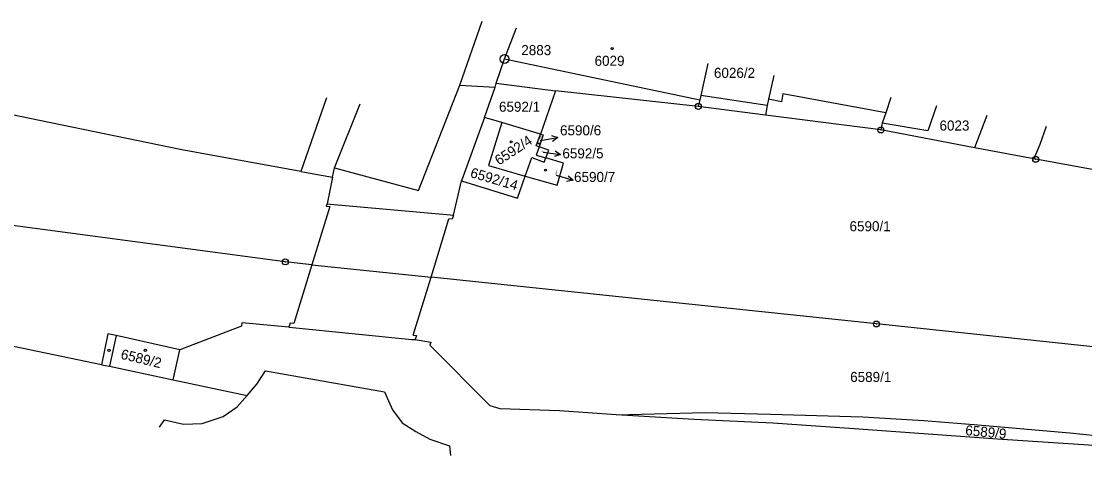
# Model space of a CAD drawing. Extents: x -825057 to -819383, y -1071633 to -1067888.
# Drawn here: x -823032.3 to -822852.6, y -1070471.3 to -1070394.3 of the extents above; entities that cross this region are included whole.
import ezdxf

# ---------------------------------------------------------------- set-up
doc = ezdxf.new("R2010")
doc.units = 0
for name, color, linetype in [('Vrstva 1', 7, 'Continuous'), ('Vrstva 16', 7, 'Continuous'), ('Vrstva 17', 7, 'Continuous'), ('Vrstva 18', 7, 'Continuous'), ('Vrstva 19', 7, 'Continuous'), ('Vrstva 24', 7, 'Continuous'), ('Vrstva 25', 7, 'Continuous'), ('Vrstva 4', 7, 'Continuous')]:
    doc.layers.add(name, color=color, linetype=linetype)

msp = doc.modelspace()

# ---------------------------------------------------------------- linework, layer by layer
at = {"layer": 'Vrstva 1'}
for p, q in [((-822958.18, -1070405.1), (-822954.43, -1070394.29)), ((-822950.64, -1070400.67), (-822948.61, -1070395.38)), ((-823005.47, -1070416), (-823077.88, -1070401.08)), ((-822952.05, -1070404.75), (-822950.64, -1070400.67)), ((-822916.25, -1070401.42), (-822917.46, -1070406.85)), ((-822905.12, -1070403.49), (-822906, -1070407.45)), ((-822965.18, -1070422.9), (-822958.18, -1070405.1)), ((-822958.18, -1070405.1), (-822952.21, -1070405.45)), ((-822952.21, -1070405.45), (-822952.05, -1070404.75)), ((-822952.05, -1070404.75), (-822942, -1070406.08)), ((-822954.04, -1070410.56), (-822952.21, -1070405.45)), ((-822942, -1070406.08), (-822944.55, -1070413.39)), ((-822917.88, -1070408.69), (-822942, -1070406.08)), ((-822917.46, -1070406.85), (-822917.63, -1070407.6)), ((-822980.71, -1070407.22), (-822985.08, -1070419.69)), ((-822979.37, -1070419.1), (-822975.05, -1070408.25)), ((-822917.63, -1070407.6), (-822917.88, -1070408.69)), ((-822906.54, -1070410.15), (-822917.88, -1070408.69)), ((-822906.23, -1070408.52), (-822906.54, -1070410.15)), ((-822906, -1070407.45), (-822906.23, -1070408.52)), ((-822885.33, -1070407.19), (-822886.19, -1070409.78)), ((-822877.65, -1070408.62), (-822879.08, -1070412.8)), ((-822954.04, -1070410.56), (-822957.9, -1070421.3)), ((-822951.08, -1070411.44), (-822954.04, -1070410.56)), ((-822887.02, -1070412.68), (-822906.54, -1070410.15)), ((-822886.19, -1070409.78), (-822886.8, -1070411.54)), ((-822869.1, -1070410.21), (-822871.2, -1070415.68)), ((-822951.08, -1070411.44), (-822953.36, -1070418.69)), ((-822944.55, -1070413.39), (-822951.08, -1070411.44)), ((-822886.8, -1070411.54), (-822887.02, -1070412.68)), ((-822879.08, -1070412.8), (-822886.8, -1070411.54)), ((-822859.11, -1070412.08), (-822860.15, -1070415.14)), ((-822945.27, -1070415.37), (-822944.55, -1070413.39)), ((-822944.12, -1070413.52), (-822944.8, -1070415.54)), ((-822944.55, -1070413.39), (-822944.12, -1070413.52)), ((-822871.2, -1070415.68), (-822887.02, -1070412.68)), ((-822999.3, -1070417.12), (-823005.47, -1070416)), ((-822944.8, -1070415.54), (-822945.27, -1070415.37)), ((-822944.8, -1070415.54), (-822945.26, -1070416.93)), ((-822943.15, -1070416.12), (-822944.8, -1070415.54)), ((-822943.63, -1070417.4), (-822943.15, -1070416.12)), ((-822861.2, -1070417.58), (-822871.2, -1070415.68)), ((-822860.15, -1070415.14), (-822861.2, -1070417.58)), ((-822989.08, -1070418.97), (-822999.3, -1070417.12)), ((-822947.14, -1070420.48), (-822946.02, -1070417.36)), ((-822946.02, -1070417.36), (-822943.91, -1070418.12)), ((-822945.26, -1070416.93), (-822943.63, -1070417.4)), ((-822943.91, -1070418.12), (-822943.63, -1070417.4)), ((-822940.65, -1070418.27), (-822943.63, -1070417.4)), ((-822860.86, -1070417.64), (-822861.2, -1070417.58)), ((-822850.06, -1070419.61), (-822860.86, -1070417.64)), ((-822985.08, -1070419.69), (-822989.08, -1070418.97)), ((-822985.08, -1070419.69), (-822979.69, -1070420.66)), ((-822979.69, -1070420.66), (-822979.37, -1070419.1)), ((-822979.37, -1070419.1), (-822965.18, -1070422.9)), ((-822953.36, -1070418.69), (-822947.14, -1070420.48)), ((-822941.76, -1070422.02), (-822940.65, -1070418.27)), ((-822979.69, -1070420.66), (-822980.63, -1070425.16)), ((-822957.9, -1070421.3), (-822948.46, -1070424.2)), ((-822948.46, -1070424.2), (-822947.14, -1070420.48)), ((-822947.14, -1070420.48), (-822941.76, -1070422.02)), ((-822987.68, -1070435), (-823086.47, -1070421.85)), ((-822980.15, -1070425.64), (-822983.18, -1070435.48)), ((-822980.63, -1070425.16), (-822980.75, -1070425.57)), ((-822980.75, -1070425.57), (-822980.15, -1070425.64)), ((-822983.18, -1070435.48), (-822987.68, -1070435)), ((-822983.18, -1070435.48), (-822986.24, -1070445.4)), ((-822983.18, -1070435.48), (-822963.05, -1070437.59)), ((-822887.77, -1070445.5), (-822963.05, -1070437.59)), ((-822995.09, -1070445.89), (-823005.51, -1070449.87)), ((-822995.03, -1070445.29), (-822995.09, -1070445.89)), ((-822987.07, -1070446.06), (-822995.03, -1070445.29)), ((-822986.85, -1070445.34), (-822987.07, -1070446.06)), ((-822987.07, -1070446.06), (-822986.47, -1070446.12)), ((-822986.24, -1070445.4), (-822986.85, -1070445.34)), ((-822986.47, -1070446.12), (-822966.27, -1070448.1)), ((-822788.26, -1070456.02), (-822887.77, -1070445.5)), ((-823018.74, -1070452.4), (-823045.87, -1070446.73)), ((-823017.65, -1070447.17), (-823018.74, -1070452.4)), ((-823016.29, -1070447.45), (-823017.65, -1070447.17)), ((-823005.51, -1070449.87), (-823016.29, -1070447.45)), ((-822966.27, -1070448.1), (-822965.74, -1070448.15)), ((-822965.74, -1070448.15), (-822963.08, -1070448.59)), ((-823006.65, -1070454.95), (-823005.51, -1070449.87)), ((-822963.08, -1070448.59), (-822963.26, -1070449.09)), ((-822963.26, -1070449.09), (-822953.06, -1070459.32)), ((-823018.74, -1070452.4), (-823017.4, -1070452.64)), ((-823017.4, -1070452.64), (-823006.65, -1070454.95)), ((-822992.52, -1070455.67), (-822991.01, -1070453.41)), ((-822991.01, -1070453.41), (-822970.89, -1070456.95)), ((-823006.65, -1070454.95), (-822994.1, -1070457.58)), ((-822994.1, -1070457.58), (-822992.52, -1070455.67)), ((-822970.89, -1070456.95), (-822969.59, -1070460.01)), ((-822995.82, -1070459.51), (-822994.1, -1070457.58)), ((-822998.21, -1070461.16), (-822995.82, -1070459.51)), ((-822969.59, -1070460.01), (-822967.92, -1070462.24)), ((-822951.35, -1070459.84), (-822953.06, -1070459.32)), ((-822941.35, -1070460.21), (-822951.35, -1070459.84)), ((-822931.79, -1070460.84), (-822941.35, -1070460.21)), ((-822931.79, -1070460.84), (-822916.73, -1070460.47)), ((-822927.98, -1070461.09), (-822931.79, -1070460.84)), ((-822918.56, -1070461.67), (-822927.98, -1070461.09)), ((-822916.73, -1070460.47), (-822905.69, -1070460.76)), ((-822905.69, -1070460.76), (-822890.07, -1070461.21)), ((-823008.97, -1070462.97), (-823008.11, -1070461.69)), ((-823008.11, -1070461.69), (-823004.87, -1070462.46)), ((-823004.87, -1070462.46), (-823001.75, -1070462.34)), ((-823001.75, -1070462.34), (-822998.21, -1070461.16)), ((-822967.92, -1070462.24), (-822965.63, -1070463.7)), ((-822905.29, -1070462.29), (-822918.56, -1070461.67)), ((-822891.54, -1070463.24), (-822905.29, -1070462.29)), ((-822890.07, -1070461.21), (-822879.77, -1070461.85)), ((-822879.77, -1070461.85), (-822871.29, -1070462.48)), ((-822871.29, -1070462.48), (-822855.09, -1070463.92)), ((-822965.63, -1070463.7), (-822963.28, -1070464.96)), ((-822867.3, -1070464.97), (-822891.54, -1070463.24)), ((-822855.09, -1070463.92), (-822780.34, -1070471.34)), ((-822963.28, -1070464.96), (-822959.93, -1070466.13)), ((-822959.93, -1070466.13), (-822959.74, -1070467.75)), ((-822847.21, -1070466.34), (-822867.3, -1070464.97))]:
    msp.add_line(p, q, dxfattribs=at)
at = {"layer": 'Vrstva 16'}
for p, q in [((-822944.6, -1070414.44), (-822941.641, -1070413.945)), ((-822944.12, -1070416.43), (-822941.146, -1070416.821)), ((-822941.91, -1070420.34), (-822939.034, -1070421.193))]:
    msp.add_line(p, q, dxfattribs=at)
for points in [[(-822942.71, -1070413.617), (-822941.641, -1070413.945), (-822942.545, -1070414.603)], [(-822942.072, -1070416.195), (-822941.146, -1070416.821), (-822942.202, -1070417.186)], [(-822939.85, -1070420.43), (-822939.034, -1070421.193), (-822940.135, -1070421.388)]]:
    msp.add_lwpolyline(points, dxfattribs=at)
at = {"layer": 'Vrstva 24'}
for centre, radius in [((-822950.64, -1070400.67), 0.75), ((-822950.64, -1070400.67), 0.0327), ((-822917.88, -1070408.69), 0.5), ((-822917.88, -1070408.69), 0.0327), ((-822887.02, -1070412.68), 0.5), ((-822887.02, -1070412.68), 0.0327), ((-822860.86, -1070417.64), 0.5), ((-822860.86, -1070417.64), 0.0327), ((-822987.68, -1070435), 0.5), ((-822987.68, -1070435), 0.0327), ((-822887.77, -1070445.5), 0.5), ((-822887.77, -1070445.5), 0.0327)]:
    msp.add_circle(centre, radius, dxfattribs=at)
at = {"layer": 'Vrstva 25'}
for centre, radius in [((-822932.45, -1070398.92), 0.175), ((-822949.52, -1070414.68), 0.175), ((-822944.84, -1070414.97), 0.117), ((-822943.7, -1070419.49), 0.175), ((-823017.48, -1070449.96), 0.175), ((-823011.34, -1070449.96), 0.175)]:
    msp.add_circle(centre, radius, dxfattribs=at)
at = {"layer": 'Vrstva 4'}
for p, q in [((-822950.64, -1070400.67), (-822917.63, -1070407.6)), ((-822906.23, -1070408.52), (-822917.46, -1070406.85)), ((-822903.6, -1070406.58), (-822903.81, -1070407.93)), ((-822886.19, -1070409.78), (-822903.6, -1070406.58)), ((-822903.81, -1070407.93), (-822906, -1070407.45)), ((-822959.26, -1070427.07), (-822957.9, -1070421.3)), ((-822980.63, -1070425.16), (-822980.03, -1070425.22)), ((-822980.03, -1070425.22), (-822959.83, -1070427.02)), ((-822963.05, -1070437.59), (-822960.03, -1070427.69)), ((-822959.49, -1070427.75), (-822960.03, -1070427.69)), ((-822959.83, -1070427.02), (-822959.26, -1070427.07)), ((-822959.26, -1070427.07), (-822959.49, -1070427.75)), ((-822966.05, -1070447.39), (-822963.05, -1070437.59)), ((-823016.29, -1070447.45), (-823017.4, -1070452.64)), ((-822966.05, -1070447.39), (-822965.52, -1070447.44)), ((-822965.52, -1070447.44), (-822965.74, -1070448.15))]:
    msp.add_line(p, q, dxfattribs=at)

# ---------------------------------------------------------------- texts
at = {"layer": 'Vrstva 16'}
for s, p in [('6590/6', (-822941.25, -1070413.59)), ('6592/5', (-822940.85, -1070417.49)), ('6590/7', (-822938.88, -1070421.48))]:
    msp.add_text(s, height=1.7, dxfattribs=at).set_placement(p)
at = {"layer": 'Vrstva 17'}
msp.add_text('2883', height=1.7, dxfattribs=at).set_placement((-822947.799, -1070400.02))
at = {"layer": 'Vrstva 18'}
for s, p in [('6592/1', (-822951.566, -1070409.6)), ('6023', (-822877.118, -1070412.78)), ('6590/1', (-822892.325, -1070429.81)), ('6589/1', (-822892.215, -1070455.31))]:
    msp.add_text(s, height=1.7, dxfattribs=at).set_placement(p)
for s, height, rotation, p in [('6592/5', 0.2, 343.8, (-822944.459, -1070416.322)), ('6592/14', 1.7, 343.6938, (-822956.551, -1070420.625)), ('6589/9', 1.7, 354.6, (-822872.82, -1070464.29))]:
    msp.add_text(s, height=height, rotation=rotation, dxfattribs=at).set_placement(p)
at = {"layer": 'Vrstva 19'}
for s, p in [('6029', (-822935.411, -1070401.83)), ('6026/2', (-822915.241, -1070403.87))]:
    msp.add_text(s, height=1.7, dxfattribs=at).set_placement(p)
for s, height, rotation, p in [('6592/4', 1.7, 33.3, (-822951.57, -1070418.72)), ('6590/6', 0.2, 71.6247, (-822944.61, -1070414.44)), ('6590/7', 0.2, 70.5717, (-822941.91, -1070420.34)), ('6589/2', 1.7, 346.5, (-823015.603, -1070451.361))]:
    msp.add_text(s, height=height, rotation=rotation, dxfattribs=at).set_placement(p)

doc.saveas('drawing.dxf')
